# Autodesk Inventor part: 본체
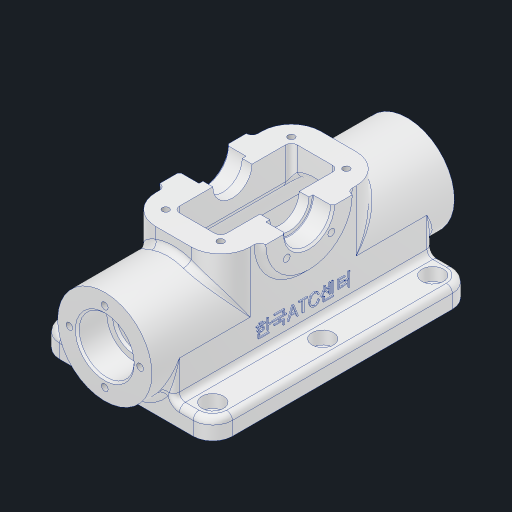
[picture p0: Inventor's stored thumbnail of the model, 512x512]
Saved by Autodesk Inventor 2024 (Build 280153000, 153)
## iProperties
Created: 2024-06
Part Number: 본체
Material: 알루미늄 6061
Document SubType Name: Modeling
Designer: kh_501
Density: 2.7 g/cm^3
Appearance: 알루미늄 - 평지
Mass: 551.548 g
Surface Area: 612.261 cm^2
Volume: 204.277 cm^3
Author: kh_501
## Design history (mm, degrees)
sketch "스케치1"
  geometry: L1 (66, 44)-(-66, 44); L2 (-66, 44)-(-66, -44); L3 (-66, -44)-(66, -44); L4 (66, -44)-(66, 44); L5 (66, 44)-(-66, -44); L6 (-66, 44)-(66, -44); 1 further point
  constraints: 12 end point, 2 midpoint, 2 parallel, 1 horizontal, 1 perpendicular
  dimensions: "d0" = 88 distance of L3.end L1.start; "d1" = 132 distance of L2.end L3.end
extrude "돌출1" new body sketch "스케치1" distance "d2" = 10; taper "d3" = 0 deg
sketch "스케치2"
  geometry: L1 (10, -44)-(10, 44) reference; L2 (0, -44)-(0, 44) reference; L3 (0, 0)-(28, 0); C1 r 24 at (28, 0); 2 further points
  constraints: 2 end point, 1 centre point, 1 coincident, 1 horizontal
  dimensions: "d4" = 28 distance of L3.start L3.end; "d5" = 48 diameter of C1
extrude "돌출2" join sketch "스케치2" stored distance "d6" = 154; taper "d7" = 0 deg
sketch "스케치3"
  geometry: L1 (-77, 52)-(77, 52) reference; L2 (-42, 59)-(42, 59); L3 (-42, 59)-(53.367, 0); L4 (42, 59)-(-30.633, 0); L5 (66, 0)-(-66, 0) reference; L6 (-42, 59)-(-42, 28); L7 (-42, 28)-(42, 28); L8 (42, 28)-(42, 59); L9 (0, 0)-(0, 28); 1 further point
  constraints: 14 end point, 2 midpoint, 2 perpendicular, 2 vertical, 1 horizontal, 1 point on line
  dimensions: "d9" = 84 distance of L2.start L2.end; "d11" = 59 distance between parallel lines of L5 L2; "d12" = 28 distance of L9.start L9.end
extrude "돌출3" join sketch "스케치3" stored distance "d13" = 48; taper "d14" = 0 deg
sketch "스케치4"
  geometry: L1 (10, -15.875)-(10, -44) reference; L2 (10, 44)-(10, 15.875) reference; L3 (0, 44)-(10, 44) reference; L4 (0, 44)-(0, -44) reference; L5 (0, -44)-(10, -44) reference; L6 (10, -15.875)-(10, -44) reference; L7 (28, -24)-(10, -24); L8 (28, 24)-(10, 24); A1 r 24 centre (28, 0) between (10, -15.875) and (28, -24) reference; A2 r 24 centre (28, 0) between (10, 15.875) and (10, -15.875) reference; 3 further points
  constraints: 4 end point, 2 perpendicular, 2 point on circle, 2 point on line, 2 tangent
extrude "돌출4" join sketch "스케치4" stored distance "d15" = 132; taper "d16" = 0 deg
sketch "스케치5"
  geometry: L1 (42, 59)-(-42, 59) reference; L2 (-66, 0)-(66, 0) reference; L3 (66, 0)-(66, 10) reference; L4 (-66, 10)-(66, 10) reference; L5 (-66, 0)-(-66, 10) reference; C1 r 22 at (0, 59); 4 further points
  constraints: 1 centre point, 1 coincident, 1 midpoint
  dimensions: "d17" = 44 diameter of C1
extrude "돌출5" join sketch "스케치5" distance "d18" = 3; taper "d19" = 0 deg
sketch "스케치6"
  geometry: L1 (0, 0)-(0, 48) reference; L2 (20, 0)-(0, 0) reference; L3 (20, 0)-(20, -3) reference; L4 (64, -3)-(20, -3) reference; L5 (64, 0)-(64, -3) reference; L6 (84, 0)-(64, 0) reference; L7 (84, 48)-(84, 0) reference; L8 (64, 48)-(84, 48) reference; L9 (64, 48)-(64, 51) reference; L10 (64, 51)-(20, 51) reference; L11 (20, 48)-(20, 51) reference; L12 (0, 48)-(20, 48) reference; L13 (12, 36)-(72, 36); L14 (72, 36)-(72, 12); L15 (72, 12)-(12, 12); L16 (12, 12)-(12, 36); L17 (12, 36)-(72, 12); L18 (72, 36)-(12, 12); 1 further point
  constraints: 12 end point, 2 midpoint, 2 parallel, 1 horizontal, 1 perpendicular
  dimensions: "d20" = 60 distance of L13.start L13.end; "d21" = 24 distance of L13.end L14.end
extrude "돌출6" cut sketch "스케치6" extent not by distance; stored distance "d22" = 0; taper "d23" = 0 deg
sketch "스케치7"
  geometry: A1 r 22 centre (0, 59) between (-22, 59) and (22, 59) reference; 2 further points
  constraints: 1 coincident
hole "구멍1" sketch "스케치7" at (0, 59) diameter "d24" = 20; stored, may be unused: countersink angle "d28" = 90 deg, drill point angle "d30" = 118 deg; dims "d25" = 6, "d26" = 24, "d27" = 10, "d29" = 10
sketch "스케치8"
  geometry: C1 r 24 at (0, 0) reference; 2 further points
  constraints: 1 coincident
hole "구멍2" sketch "스케치8" at (0, 0) diameter "d31" = 22; stored, may be unused: countersink angle "d35" = 90 deg, drill point angle "d37" = 118 deg; dims "d32" = 6, "d33" = 28, "d34" = 15, "d36" = 8
sketch "스케치9"
  geometry: L1 (0, 0)-(0, 18); C1 r 14 at (0, 0) reference; C2 r 24 at (0, 0) reference; A1 r 18 centre (0, 0) between (0, 18) and (0, 18); 1 further point
  constraints: 2 end point, 2 point on circle, 1 centre point, 1 coincident, 1 vertical
  dimensions: "d38" = 36 diameter of A1
hole "구멍3" sketch "스케치9" at (0, 18) diameter "d39" = 3.45873; stored, may be unused: countersink angle "d43" = 90 deg, drill point angle "d45" = 118 deg; dims "d40" = 8, "d41" = 28, "d42" = 15, "d44" = 10
sketch "스케치10"
  geometry: L1 (-12, 59)-(-22, 59) reference; L2 (22, 59)-(12, 59) reference; L3 (0, 59)-(0, 43); L4 (0, 59)-(-11.314, 47.686); L5 (0, 59)-(11.314, 47.686); A1 r 12 centre (0, 59) between (-12, 59) and (12, 59) reference; A2 r 22 centre (0, 59) between (-22, 59) and (22, 59) reference; A3 r 16 centre (0, 59) between (0, 43) and (-11.314, 47.686); 3 further points
  constraints: 6 end point, 3 coincident, 3 point on circle, 1 centre point, 1 vertical
  dimensions: "d49" = 32 diameter of A3; "d50" = 45 deg angle of L3 L4; "d51" = 45 deg angle of L5 L3
hole "구멍4" sketch "스케치10" at (-11.314, 47.686), (11.314, 47.686) diameter "d52" = 3.45873; stored, may be unused: countersink angle "d56" = 90 deg, drill point angle "d58" = 118 deg; dims "d53" = 8, "d54" = 4, "d55" = 2, "d57" = 10
sketch "스케치11"
  geometry: L1 (-30, 51)-(-30, 41) reference; L2 (-30, 41)-(-32, 41) reference; L3 (-32, 41)-(-32, 36) reference; L4 (-32, 36)-(-12, 36) reference; L5 (-12, 36)-(-12, 12) reference; L6 (-12, 12)-(-32, 12) reference; L7 (-32, 12)-(-32, 7) reference; L8 (-32, 7)-(-30, 7) reference; L9 (-30, 7)-(-30, -3) reference; L10 (-20, -3)-(-30, -3) reference; L11 (-20, 0)-(-20, -3) reference; L12 (0, 0)-(-20, 0) reference; L13 (0, 48)-(0, 0) reference; L14 (-20, 48)-(0, 48) reference; L15 (-20, 48)-(-20, 51) reference; L16 (-20, 51)-(-30, 51) reference; L17 (-54, 41)-(-54, 51) reference; L18 (-54, 51)-(-64, 51) reference; L19 (-64, 48)-(-64, 51) reference; L20 (-84, 48)-(-64, 48) reference; L21 (-84, 0)-(-84, 48) reference; L22 (-64, 0)-(-84, 0) reference; L23 (-64, 0)-(-64, -3) reference; L24 (-54, -3)-(-64, -3) reference; L25 (-54, -3)-(-54, 7) reference; L26 (-54, 7)-(-52, 7) reference; L27 (-52, 7)-(-52, 12) reference; L28 (-52, 12)-(-72, 12) reference; L29 (-72, 12)-(-72, 36) reference; L30 (-72, 36)-(-52, 36) reference; L31 (-52, 36)-(-52, 41) reference; L32 (-52, 41)-(-54, 41) reference; L33 (-74, 38)-(-10, 38); L34 (-10, 38)-(-10, 10); L35 (-10, 10)-(-74, 10); L36 (-74, 10)-(-74, 38); L37 (-74, 38)-(-10, 10); L38 (-10, 38)-(-74, 10); 5 further points
  constraints: 12 end point, 4 coincident, 2 midpoint, 2 parallel, 1 horizontal, 1 perpendicular
  dimensions: "d59" = 64 distance of L33.start L33.end; "d60" = 28 distance of L33.end L34.end
hole "구멍5" sketch "스케치11" at (-74, 38), (-74, 10), (-10, 10), (-10, 38) diameter "d61" = 3.45873; stored, may be unused: countersink angle "d65" = 90 deg, drill point angle "d67" = 118 deg; dims "d62" = 8, "d63" = 4, "d64" = 2, "d66" = 10
fillet "모깎기1" dims "d68" = 15
sketch "스케치12"
  geometry: L1 (-27, 28)-(-27, 59) reference; L2 (-66, 28)-(-27, 28) reference; L3 (-66, 10)-(-66, 28) reference; L4 (66, 10)-(-66, 10) reference; L5 (66, 28)-(66, 10) reference; L6 (27, 28)-(66, 28) reference; L7 (27, 59)-(27, 28) reference; L8 (27, 59)-(22, 59) reference; L9 (-22, 59)-(-27, 59) reference; L10 (-66, 0)-(66, 0) reference; L11 (0, 0)-(0, 20); A1 r 22 centre (0, 59) between (-22, 59) and (22, 59) reference; 1 further point
  constraints: 2 end point, 1 coincident, 1 vertical, 1 other
  dimensions: "d69" = 20 distance of L11.start L11.end
feature "엠보싱1" sketch "스케치12" dims "d70" = 0.5, "d71" = 0
fillet "모깎기2" dims "d72" = 10
sketch "스케치13"
  geometry: L1 (56, 44)-(-56, 44) reference; L2 (66, -34)-(66, 34) reference; L3 (-56, -44)-(56, -44) reference; L4 (-66, 34)-(-66, -34) reference; L5 (30, -12)-(30, 12) reference; L6 (30, 12)-(-30, 12) reference; L7 (-30, 12)-(-30, -12) reference; L8 (-30, -12)-(30, -12) reference; L9 (-56, 34)-(56, 34); L10 (56, 34)-(56, -34); L11 (0, 34)-(0, -34); A1 r 10 centre (-56, 34) between (-56, 44) and (-66, 34) reference; A2 r 10 centre (56, 34) between (66, 34) and (56, 44) reference; A3 r 10 centre (56, -34) between (56, -44) and (66, -34) reference; A4 r 10 centre (-56, -34) between (-66, -34) and (-56, -44) reference; 4 further points
  constraints: 6 coincident, 6 end point, 2 vertical, 1 horizontal, 1 midpoint
hole "구멍6" sketch "스케치13" at (-56, 34), (-56, -34), (56, -34), (56, 34), (0, -34), (0, 34) diameter "d73" = 6.6; stored, may be unused: countersink angle "d77" = 90 deg, drill point angle "d79" = 118 deg; dims "d74" = 8, "d75" = 11, "d76" = 6.6, "d78" = 10
chamfer "모따기1" distance "d80" = 1; stored, may be unused: second distance "d81" = 2, angle "d82" = 45 deg
fillet "모깎기3" dims "d83" = 0.3
sketch "스케치14"
  geometry: L1 (0, 34)-(0, -34) reference; L2 (28, -18)-(0, -18); L3 (28, 18)-(0, 18); C1 r 11 at (28, 0) reference; A1 r 18 centre (28, 0) between (28, -18) and (28, 18); 1 further point
  constraints: 4 end point, 2 perpendicular, 2 point on circle, 2 point on line, 2 tangent, 1 centre point, 1 coincident
  dimensions: "d84" = 36 diameter of A1
extrude "돌출7" cut sketch "스케치14" stored distance "d85" = 120; taper "d86" = 0 deg
fillet "모깎기4" dims "d87" = 3
fillet "모깎기5" dims "d88" = 3
fillet "모깎기6" dims "d89" = 3
fillet "모깎기7" dims "d90" = 3
fillet "모깎기8" dims "d91" = 3
fillet "모깎기9" dims "d92" = 3
fillet "모깎기10" dims "d93" = 3
node "솔리드1"
mirror "미러1"
mirror "미러2"
mirror "미러3"
pattern_circular "원형 패턴1" dims angle "d47" = 360 deg
mirror "미러4"
mirror "미러5"
node "투영된 루프1"
node "투영된 루프2"
node "투영된 루프3"
node "투영된 루프4"
node "투영된 루프5"
node "투영된 루프6"
node "투영된 루프7"
node "투영된 루프8"
node "투영된 루프9"
feature "A9D066F2-1C7D-4E18-AEED-F7BC21143FA4" dims "d24" = 20, "d25" = 6, "d26" = 24, "d27" = 10, "d28" = 90 deg, "d29" = 10, "d30" = 118 deg
